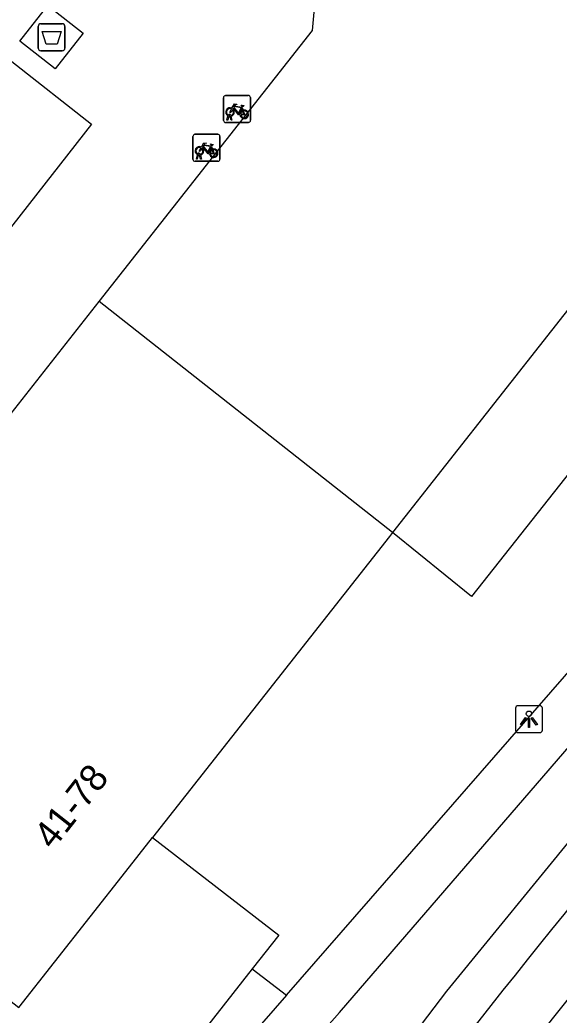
# Model space of a CAD drawing. Extents: x 160304 to 160954, y 383686 to 384161.
# Drawn here: x 160838.04 to 160858.01, y 383795.32 to 383832.18 of the extents above; entities that cross this region are included whole.
import ezdxf

# ---------------------------------------------------------------- set-up
doc = ezdxf.new("R2010")
doc.units = 0
for name, color, linetype in [('IMGEO_Afval_apart_plaats', 7, 'Continuous'), ('IMGEO_Fietsenrek', 7, 'Continuous'), ('IMGEO_Fietspad_open', 7, 'Continuous'), ('IMGEO_Groenvoorziening', 7, 'Continuous'), ('IMGEO_Lichtpunt', 7, 'Continuous'), ('IMGEO_Pand', 7, 'Continuous'), ('IMGEO_Pand_nummerreeks', 7, 'Continuous'), ('IMGEO_Voetpad_gesloten', 7, 'Continuous'), ('IMGEO_Voetpad_open', 7, 'Continuous')]:
    doc.layers.add(name, color=color, linetype=linetype)

msp = doc.modelspace()

# ---------------------------------------------------------------- linework, layer by layer
at = {"layer": 'IMGEO_Afval_apart_plaats'}
for p, q in [((160838.717, 383831.132), (160838.717, 383831.932)), ((160838.717, 383831.932), (160838.717, 383831.132)), ((160838.817, 383832.032), (160839.607, 383832.032)), ((160839.607, 383832.032), (160838.817, 383832.032)), ((160839.707, 383831.932), (160839.707, 383831.132)), ((160839.707, 383831.132), (160839.707, 383831.932)), ((160839.607, 383831.032), (160838.817, 383831.032)), ((160838.817, 383831.032), (160839.607, 383831.032))]:
    msp.add_line(p, q, dxfattribs=at)
msp.add_lwpolyline([(160838.86, 383831.746), (160839.564, 383831.746), (160839.415, 383831.276), (160839.009, 383831.276), (160838.86, 383831.746)], dxfattribs=at)
for centre, start, end in [((160838.817, 383831.932), 90, 180), ((160838.817, 383831.932), 90, 180), ((160839.607, 383831.932), 0, 90), ((160839.607, 383831.932), 360, 90), ((160838.817, 383831.132), 180, 270), ((160838.817, 383831.132), 180, 270), ((160839.607, 383831.132), 270, 0), ((160839.607, 383831.132), 270, 0)]:
    msp.add_arc(centre, 0.1, start, end, dxfattribs=at)
at = {"layer": 'IMGEO_Fietsenrek'}
for p, q in [((160845.582, 383828.452), (160845.582, 383829.293)), ((160845.582, 383829.293), (160845.582, 383828.452)), ((160845.657, 383829.377), (160846.498, 383829.377)), ((160846.498, 383829.377), (160845.657, 383829.377)), ((160846.582, 383829.302), (160846.582, 383828.461)), ((160846.582, 383828.461), (160846.582, 383829.302)), ((160846.269, 383828.926), (160846.305, 383828.831)), ((160845.709, 383828.461), (160845.748, 383828.621)), ((160845.743, 383828.461), (160845.709, 383828.461)), ((160845.778, 383828.609), (160845.743, 383828.461)), ((160845.82, 383828.633), (160845.819, 383828.637)), ((160845.861, 383828.461), (160845.827, 383828.603)), ((160845.851, 383828.644), (160845.852, 383828.637)), ((160845.859, 383828.607), (160845.894, 383828.461)), ((160845.894, 383828.461), (160845.861, 383828.461)), ((160846.507, 383828.377), (160845.666, 383828.377)), ((160845.666, 383828.377), (160846.507, 383828.377)), ((160844.45, 383827.014), (160844.45, 383827.855)), ((160844.45, 383827.855), (160844.45, 383827.014)), ((160844.525, 383827.939), (160845.366, 383827.939)), ((160845.366, 383827.939), (160844.525, 383827.939)), ((160845.45, 383827.864), (160845.45, 383827.023)), ((160845.45, 383827.023), (160845.45, 383827.864)), ((160845.137, 383827.488), (160845.173, 383827.393)), ((160844.577, 383827.023), (160844.616, 383827.183)), ((160844.611, 383827.023), (160844.577, 383827.023)), ((160844.646, 383827.171), (160844.611, 383827.023)), ((160844.688, 383827.195), (160844.687, 383827.199)), ((160844.729, 383827.023), (160844.695, 383827.165)), ((160844.719, 383827.206), (160844.72, 383827.199)), ((160844.727, 383827.169), (160844.762, 383827.023)), ((160844.762, 383827.023), (160844.729, 383827.023)), ((160845.375, 383826.939), (160844.534, 383826.939)), ((160844.534, 383826.939), (160845.375, 383826.939))]:
    msp.add_line(p, q, dxfattribs=at)
for points in [[(160845.916, 383828.851), (160845.864, 383828.761), (160845.824, 383828.736), (160845.825, 383828.783), (160845.88, 383828.877)], [(160845.895, 383828.903), (160845.99, 383829.067), (160846.076, 383829.053), (160846.078, 383829.044), (160846.022, 383829.033), (160845.995, 383828.988), (160846.251, 383828.947)], [(160846.191, 383828.659), (160846.141, 383828.659), (160845.95, 383828.91), (160845.931, 383828.878)], [(160846.238, 383828.922), (160845.981, 383828.963), (160845.964, 383828.934), (160846.131, 383828.714), (160846.238, 383828.922)], [(160846.286, 383828.824), (160846.256, 383828.901), (160846.147, 383828.683), (160846.19, 383828.683)], [(160846.22, 383828.683), (160846.34, 383828.682), (160846.296, 383828.796)], [(160846.316, 383828.803), (160846.371, 383828.658), (160846.221, 383828.658)], [(160846.251, 383828.947), (160846.276, 383828.996), (160846.27, 383829), (160846.247, 383829.004), (160846.235, 383829.011), (160846.234, 383829.014), (160846.236, 383829.019), (160846.331, 383829.004), (160846.333, 383828.994), (160846.323, 383828.981), (160846.311, 383828.975), (160846.297, 383828.981), (160846.269, 383828.926)], [(160844.784, 383827.413), (160844.732, 383827.323), (160844.692, 383827.298), (160844.693, 383827.345), (160844.748, 383827.439)], [(160844.763, 383827.465), (160844.858, 383827.629), (160844.944, 383827.615), (160844.946, 383827.606), (160844.89, 383827.595), (160844.863, 383827.55), (160845.119, 383827.509)], [(160845.059, 383827.221), (160845.009, 383827.221), (160844.818, 383827.472), (160844.799, 383827.44)], [(160845.106, 383827.484), (160844.849, 383827.525), (160844.832, 383827.496), (160844.999, 383827.276), (160845.106, 383827.484)], [(160845.154, 383827.386), (160845.124, 383827.463), (160845.015, 383827.245), (160845.058, 383827.245)], [(160845.088, 383827.245), (160845.208, 383827.244), (160845.164, 383827.358)], [(160845.184, 383827.365), (160845.239, 383827.22), (160845.089, 383827.22)], [(160845.119, 383827.509), (160845.144, 383827.558), (160845.138, 383827.562), (160845.115, 383827.566), (160845.103, 383827.573), (160845.102, 383827.576), (160845.104, 383827.581), (160845.199, 383827.566), (160845.201, 383827.556), (160845.191, 383827.543), (160845.179, 383827.537), (160845.165, 383827.543), (160845.137, 383827.488)]]:
    msp.add_lwpolyline(points, dxfattribs=at)
for centre, radius, start, end in [((160845.66, 383829.299), 0.0779, 92.4484, 184.2845), ((160845.66, 383829.299), 0.0779, 92.4484, 184.2845), ((160846.504, 383829.299), 0.0779, 2.4484, 94.2845), ((160846.504, 383829.299), 0.0779, 2.4484, 94.2845), ((160845.822, 383828.762), 0.159, 62.6766, 242.1369), ((160845.822, 383828.762), 0.129, 63.3192, 238.903), ((160845.822, 383828.762), 0.129, 283.6043, 43.4302), ((160845.822, 383828.762), 0.159, 283.5766, 46.6042), ((160846.349, 383828.678), 0.159, 113.3408, 178.3217), ((160846.349, 383828.678), 0.159, 187.0065, 105.7708), ((160846.349, 383828.678), 0.129, 113.923, 177.9556), ((160846.349, 383828.678), 0.129, 188.6715, 104.5883), ((160845.66, 383828.455), 0.0779, 182.4484, 274.2845), ((160845.66, 383828.455), 0.0779, 182.4484, 274.2845), ((160845.802, 383828.633), 0.0499, 12.8025, 158.6934), ((160845.822, 383828.762), 0.159, 253.9967, 271.7867), ((160845.802, 383828.633), 0.0174, 12.8025, 163.4502), ((160845.822, 383828.762), 0.129, 253.415, 269.0204), ((160846.504, 383828.455), 0.0779, 272.4484, 4.2845), ((160846.504, 383828.455), 0.0779, 272.4484, 4.2845), ((160844.528, 383827.861), 0.0779, 92.4484, 184.2845), ((160844.528, 383827.861), 0.0779, 92.4484, 184.2845), ((160845.372, 383827.861), 0.0779, 2.4484, 94.2845), ((160845.372, 383827.861), 0.0779, 2.4484, 94.2845), ((160844.69, 383827.324), 0.159, 62.6766, 242.1369), ((160844.69, 383827.324), 0.129, 63.3192, 238.903), ((160844.69, 383827.324), 0.129, 283.6043, 43.4302), ((160844.69, 383827.324), 0.159, 283.5766, 46.6042), ((160845.217, 383827.24), 0.159, 113.3408, 178.3217), ((160845.217, 383827.24), 0.159, 187.0065, 105.7708), ((160845.217, 383827.24), 0.129, 113.923, 177.9556), ((160845.217, 383827.24), 0.129, 188.6715, 104.5883), ((160844.528, 383827.017), 0.0779, 182.4484, 274.2845), ((160844.528, 383827.017), 0.0779, 182.4484, 274.2845), ((160844.67, 383827.195), 0.0499, 12.8025, 158.6934), ((160844.69, 383827.324), 0.159, 253.9967, 271.7867), ((160844.67, 383827.195), 0.0174, 12.8025, 163.4502), ((160844.69, 383827.324), 0.129, 253.415, 269.0204), ((160845.372, 383827.017), 0.0779, 272.4484, 4.2845), ((160845.372, 383827.017), 0.0779, 272.4484, 4.2845)]:
    msp.add_arc(centre, radius, start, end, dxfattribs=at)
at = {"layer": 'IMGEO_Fietspad_open'}
for centre, radius, start, end in [((161101.821, 383600.979), 313.991, 136.82328, 145.22029), ((161080.422, 383618.144), 284.468, 137.93366, 146.11352)]:
    msp.add_arc(centre, radius, start, end, dxfattribs=at)
at = {"layer": 'IMGEO_Groenvoorziening'}
for points in [[(160857.274, 383875.816), (160862.472, 383878.595), (160870.895, 383862.33), (160867.154, 383826.483), (160854.767, 383810.821), (160851.843, 383813.196)], [(160842.953, 383801.897), (160847.628, 383798.289), (160846.646, 383797.038)], [(160846.646, 383797.038), (160830.106, 383775.963), (160830.29, 383775.722)], [(160846.646, 383797.038), (160847.919, 383796.056)]]:
    msp.add_lwpolyline(points, dxfattribs=at)
at = {"layer": 'IMGEO_Lichtpunt'}
for p, q in [((160856.396, 383806.685), (160856.396, 383805.878)), ((160856.396, 383806.685), (160856.396, 383805.878)), ((160857.298, 383806.78), (160856.49, 383806.78)), ((160857.298, 383806.78), (160856.49, 383806.78)), ((160857.392, 383805.878), (160857.392, 383806.685)), ((160857.392, 383805.878), (160857.392, 383806.685)), ((160856.49, 383805.784), (160857.298, 383805.784)), ((160856.49, 383805.784), (160857.298, 383805.784))]:
    msp.add_line(p, q, dxfattribs=at)
for points in [[(160856.77, 383806.349), (160856.809, 383806.321), (160856.621, 383806.059), (160856.583, 383806.086), (160856.77, 383806.349)], [(160856.982, 383806.321), (160857.02, 383806.348), (160857.207, 383806.086), (160857.168, 383806.058), (160856.982, 383806.321)], [(160856.872, 383806.301), (160856.919, 383806.301), (160856.919, 383805.979), (160856.872, 383805.979), (160856.872, 383806.301)]]:
    msp.add_lwpolyline(points, dxfattribs=at)
msp.add_circle((160856.895, 383806.483), 0.0994, dxfattribs=at)
for centre, start, end in [((160856.49, 383806.685), 90, 180), ((160856.49, 383806.685), 90, 180), ((160857.298, 383806.685), 0, 90), ((160857.298, 383806.685), 0, 90), ((160856.49, 383805.878), 180, 270), ((160856.49, 383805.878), 180, 270), ((160857.298, 383805.878), 270, 0), ((160857.298, 383805.878), 270, 360)]:
    msp.add_arc(centre, 0.0946, start, end, dxfattribs=at)
at = {"layer": 'IMGEO_Pand'}
for points in [[(160840.979, 383821.745), (160848.881, 383831.788), (160849.206, 383835.474), (160848.984, 383835.493), (160846.219, 383837.433), (160846.911, 383845.265)], [(160863.738, 383843.778), (160862.62, 383831.129), (160863.763, 383830.681), (160860.673, 383822.784), (160859.69, 383823.168), (160851.843, 383813.196)], [(160827.792, 383804.985), (160840.979, 383821.745)], [(160851.843, 383813.196), (160840.979, 383821.745)], [(160851.843, 383813.196), (160851.726, 383813.047), (160842.953, 383801.897)], [(160832.747, 383791.894), (160836.555, 383796.734), (160837.998, 383795.599), (160841.97, 383800.647), (160842.953, 383801.897)]]:
    msp.add_lwpolyline(points, dxfattribs=at)
at = {"layer": 'IMGEO_Voetpad_gesloten'}
msp.add_lwpolyline([(160838.042, 383831.383), (160839.073, 383832.703), (160840.382, 383831.68), (160839.351, 383830.361), (160838.042, 383831.383)], dxfattribs=at)
at = {"layer": 'IMGEO_Voetpad_open'}
for points in [[(160837.742, 383830.632), (160840.69, 383828.317), (160826.73, 383810.469), (160823.8, 383812.776)], [(160847.919, 383796.056), (160858.712, 383808.442), (160875.547, 383827.875), (160877.717, 383830.549)], [(160875.807, 383821.459), (160873.125, 383818.297), (160864.338, 383808.756), (160858.767, 383802.234), (160853.84, 383796.208), (160847.633, 383788.041), (160844.965, 383784.351), (160841.939, 383779.888), (160839.455, 383776.223), (160835.377, 383769.709), (160831.252, 383762.844), (160822.902, 383750), (160820.261, 383745.938)], [(160840.438, 383784.74), (160849.874, 383795.418), (160871.102, 383819.99)], [(160847.919, 383796.056), (160839.16, 383786.027), (160831.043, 383775.115)]]:
    msp.add_lwpolyline(points, dxfattribs=at)

# ---------------------------------------------------------------- texts
at = {"layer": 'IMGEO_Pand_nummerreeks'}
msp.add_text('41-78', height=1, rotation=51.8584, dxfattribs=at).set_placement((160839.264, 383801.411))

doc.saveas('drawing.dxf')
